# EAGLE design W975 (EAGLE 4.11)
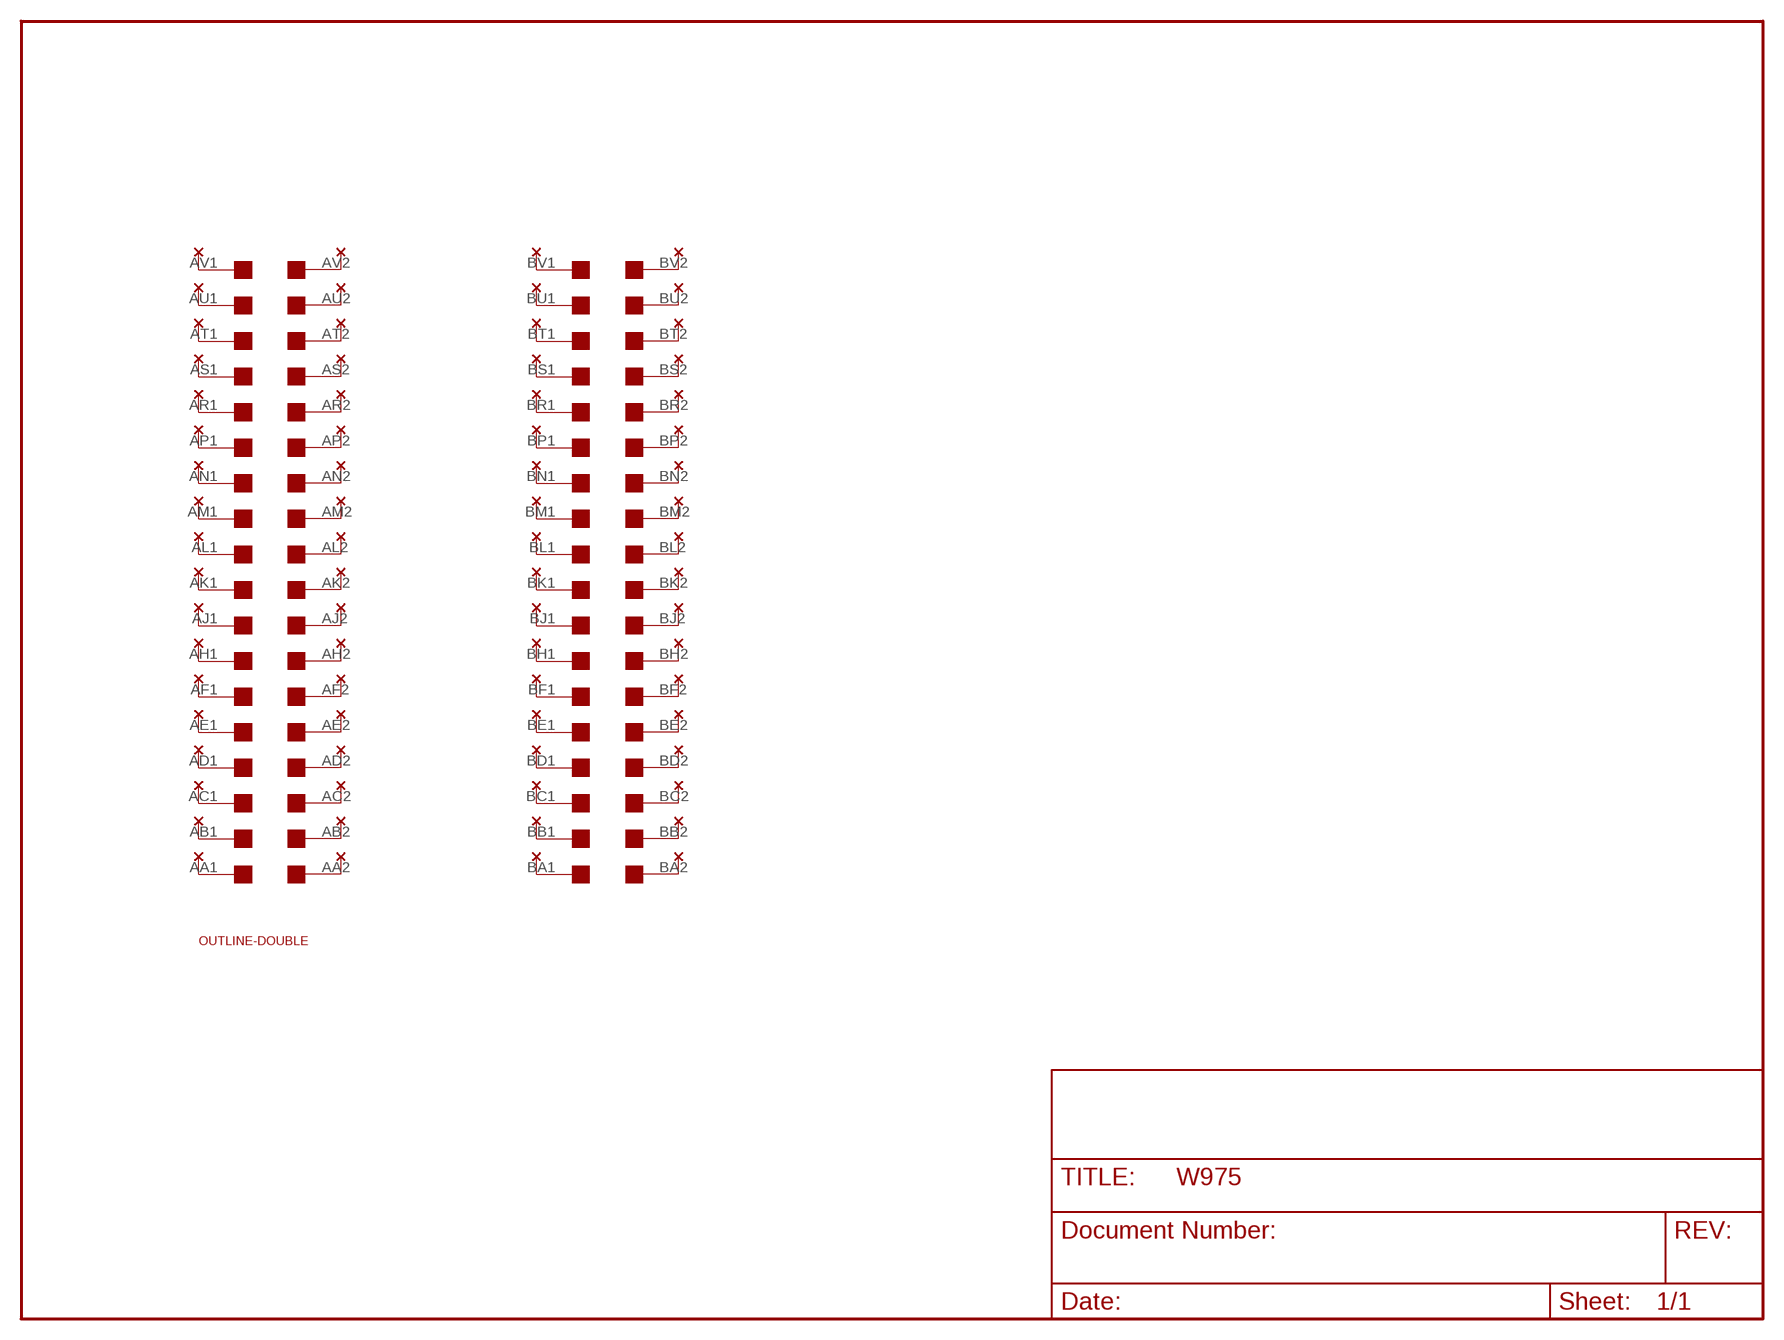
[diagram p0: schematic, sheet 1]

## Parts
A  A  THRU-HOLE2  [THRU-HOLE2]
B  B  THRU-HOLE2  [THRU-HOLE2]
U$1  OUTLINE-DOUBLE  [DOUBLE]
U$2  DOUBLE  [EDGE-CON4]

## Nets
N$1: A.K2 U$2.AK2
N$2: A.J2 U$2.AJ2
N$3: A.H2 U$2.AH2
N$4: A.L2 U$2.AL2
N$5: A.M2 U$2.AM2
N$6: A.N2 U$2.AN2
N$7: A.P2 U$2.AP2
N$8: A.F2 U$2.AF2
N$9: A.E2 U$2.AE2
N$10: A.D2 U$2.AD2
N$11: A.C2 U$2.AC2
N$12: A.R2 U$2.AR2
N$13: A.S2 U$2.AS2
N$14: A.B2 U$2.AB2
N$15: A.A2 U$2.AA2
N$16: A.T2 U$2.AT2
N$17: A.U2 U$2.AU2
N$18: A.V2 U$2.AV2
N$19: A.A1 U$2.AA1
N$20: A.V1 U$2.AV1
N$21: A.U1 U$2.AU1
N$22: A.T1 U$2.AT1
N$23: A.S1 U$2.AS1
N$24: A.R1 U$2.AR1
N$25: A.P1 U$2.AP1
N$26: A.N1 U$2.AN1
N$27: A.M1 U$2.AM1
N$28: A.L1 U$2.AL1
N$29: A.K1 U$2.AK1
N$30: A.J1 U$2.AJ1
N$31: A.H1 U$2.AH1
N$32: A.F1 U$2.AF1
N$33: A.E1 U$2.AE1
N$34: A.D1 U$2.AD1
N$35: A.C1 U$2.AC1
N$36: A.B1 U$2.AB1
N$37: B.K2 U$2.BK2
N$38: B.J2 U$2.BJ2
N$39: B.H2 U$2.BH2
N$40: B.L2 U$2.BL2
N$41: B.M2 U$2.BM2
N$42: B.N2 U$2.BN2
N$43: B.P2 U$2.BP2
N$44: B.F2 U$2.BF2
N$45: B.E2 U$2.BE2
N$46: B.D2 U$2.BD2
N$47: B.C2 U$2.BC2
N$48: B.R2 U$2.BR2
N$49: B.S2 U$2.BS2
N$50: B.B2 U$2.BB2
N$51: B.A2 U$2.BA2
N$52: B.T2 U$2.BT2
N$53: B.U2 U$2.BU2
N$54: B.V2 U$2.BV2
N$55: B.A1 U$2.BA1
N$56: B.V1 U$2.BV1
N$57: B.U1 U$2.BU1
N$58: B.T1 U$2.BT1
N$59: B.S1 U$2.BS1
N$60: B.R1 U$2.BR1
N$61: B.P1 U$2.BP1
N$62: B.N1 U$2.BN1
N$63: B.M1 U$2.BM1
N$64: B.L1 U$2.BL1
N$65: B.K1 U$2.BK1
N$66: B.J1 U$2.BJ1
N$67: B.H1 U$2.BH1
N$68: B.F1 U$2.BF1
N$69: B.E1 U$2.BE1
N$70: B.D1 U$2.BD1
N$71: B.C1 U$2.BC1
N$72: B.B1 U$2.BB1

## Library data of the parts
A B = dec-con:THRU-HOLE2: Thru-Hole addition to double-sided edge connector.
U$1 = dec-con:OUTLINE-*: Board outlines for DEC boards.
U$2 = dec-con:DOUBLE: Double-Height DEC board

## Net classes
0 default: width 0.508 mm, drill 0.508 mm

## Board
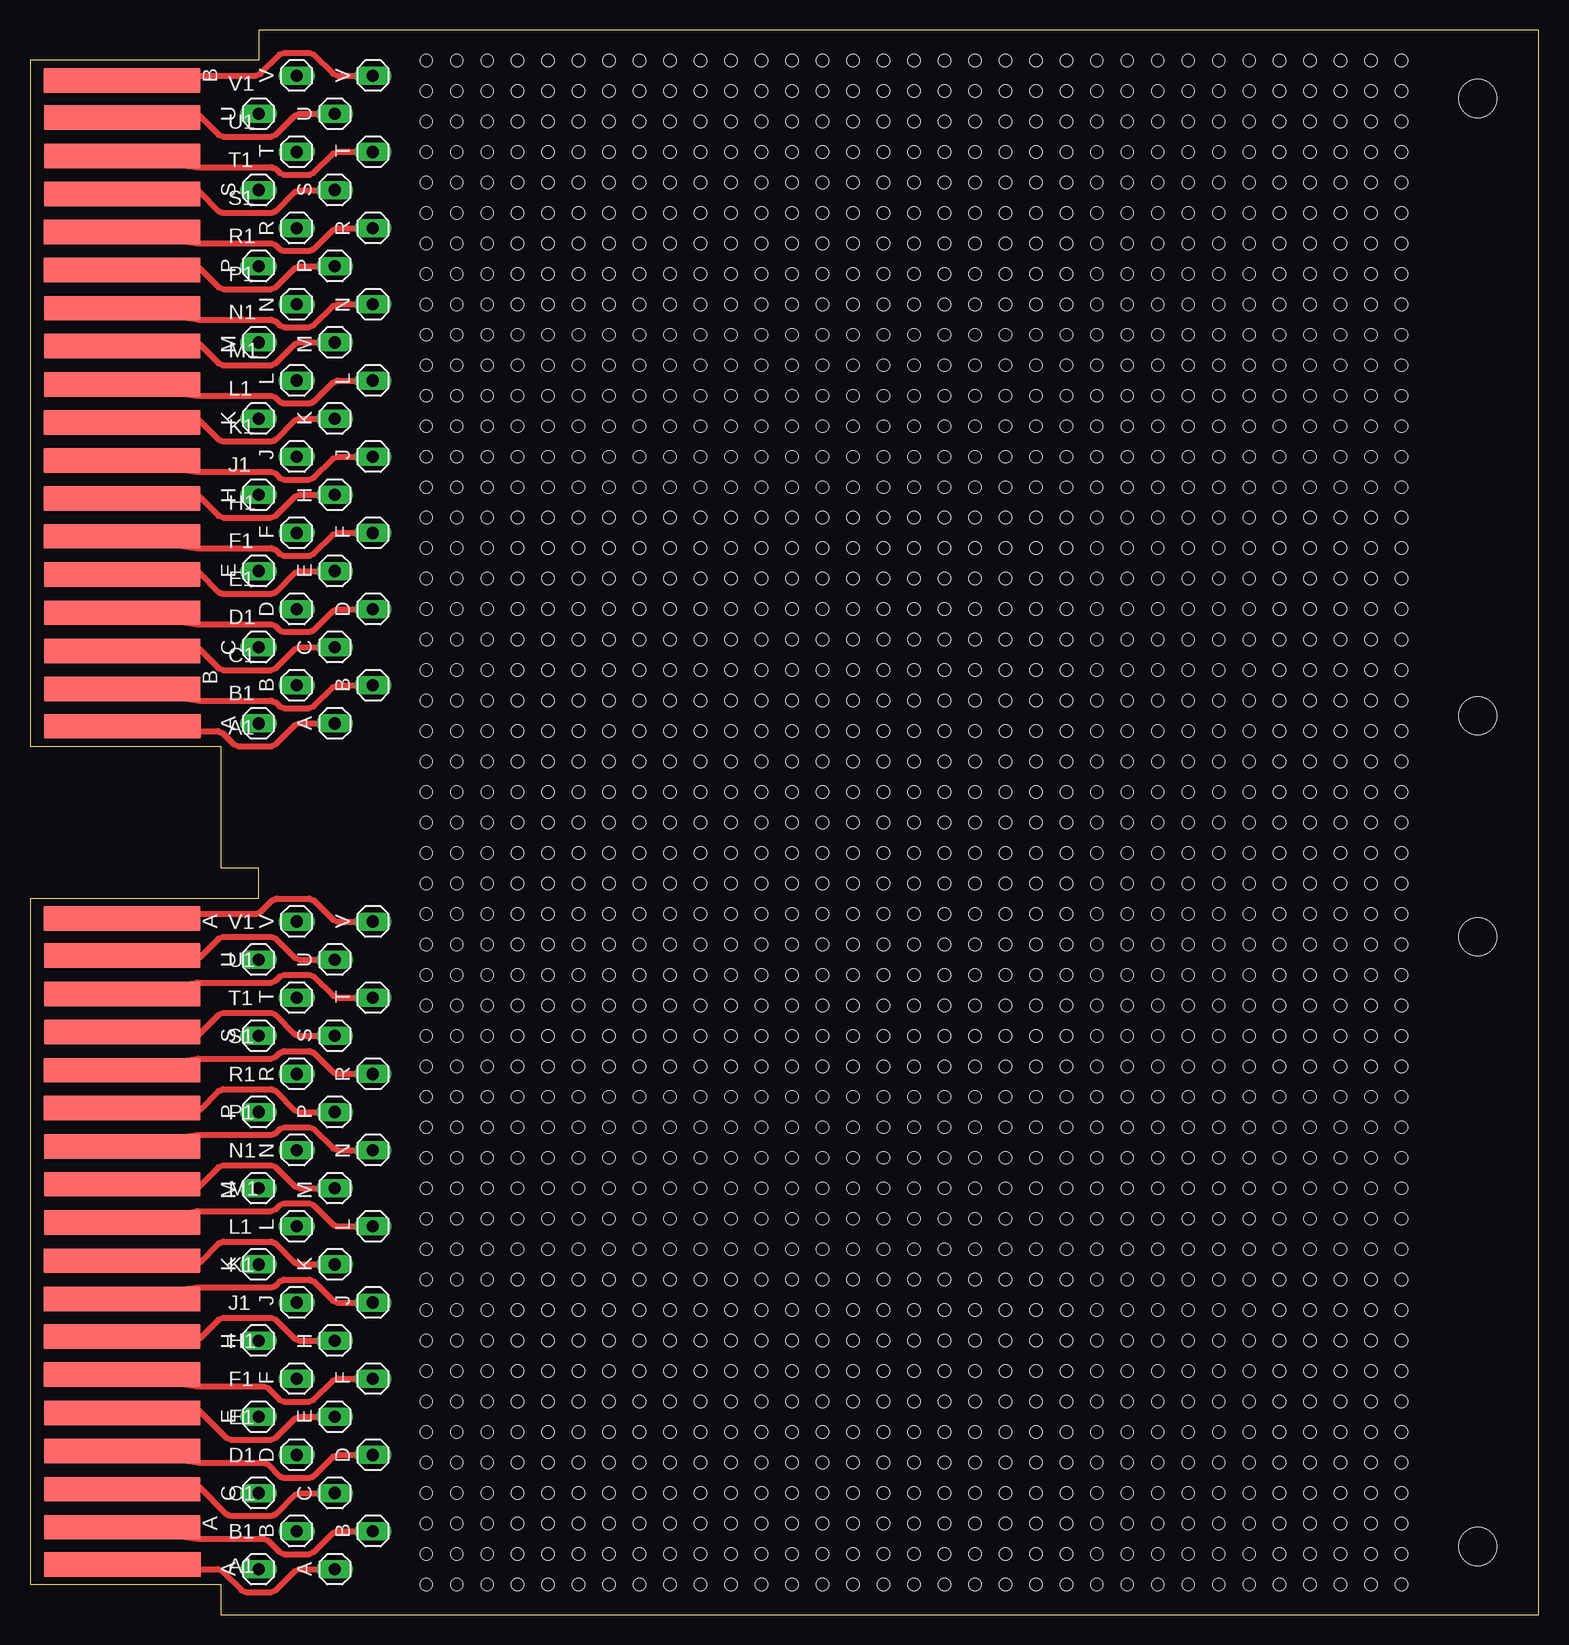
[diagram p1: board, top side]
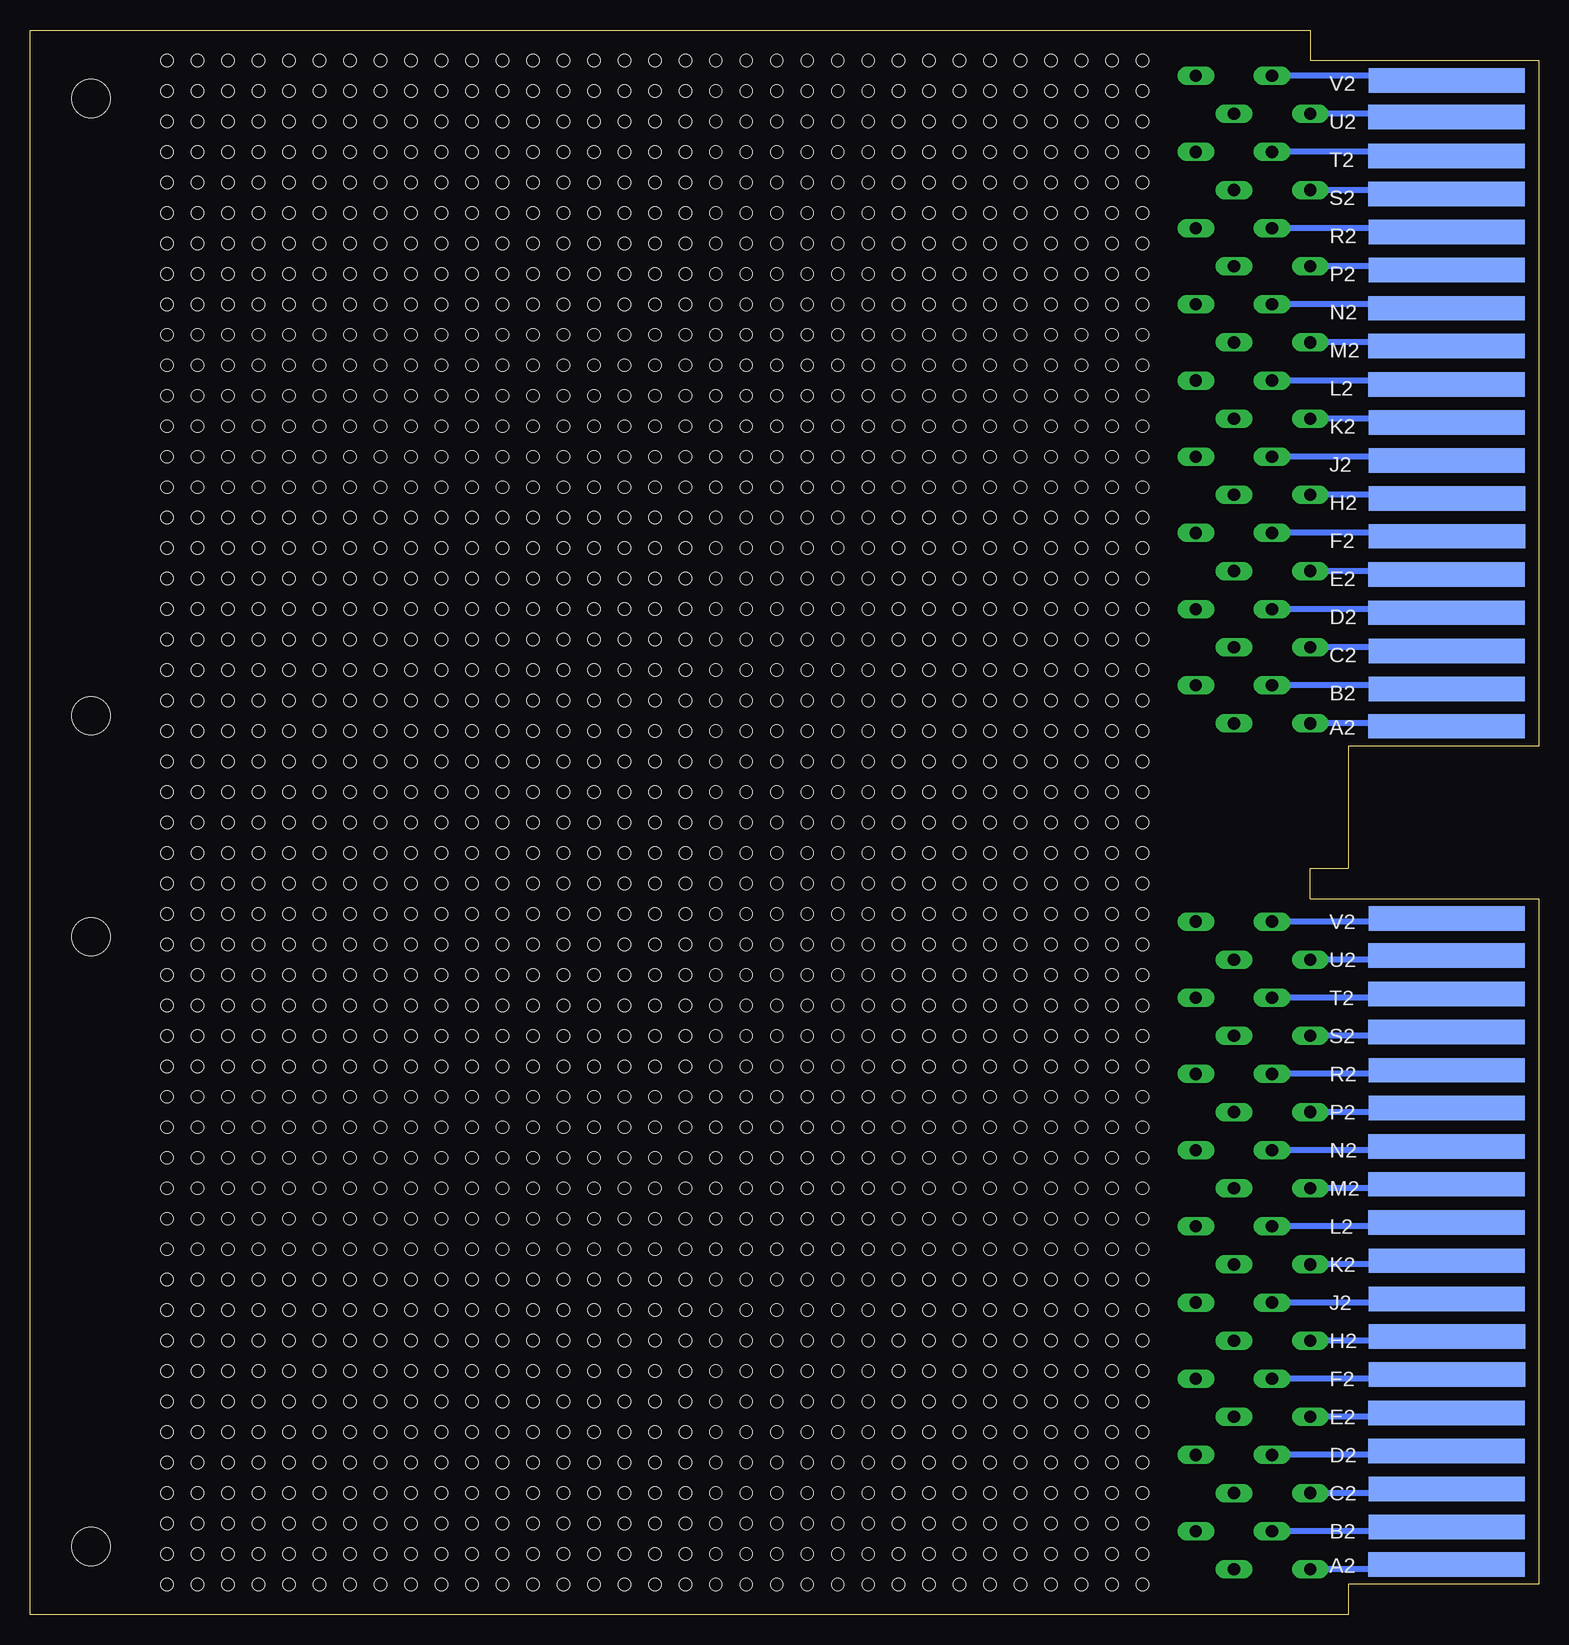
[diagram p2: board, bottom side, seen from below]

Size 125.73 x 132.08 mm. Coordinates in mm from the lower left corner, seen from the top.
Copper layers (1*16): Top 0.035mm / dielectric 1.5mm / Bottom 0.035mm
Design rules "15mils": minimum track width 15mil, minimum drill 24mil, track to track 15mil, track to pad 10mil, pad to pad 10mil, via to via 10mil, smd to smd 10mil, copper to edge 25mil, drill to drill 10mil, minimum pad ring 10mil, minimum via ring 8mil, stop-mask expansion 0mil, vias tented up to drill 0mil, thermal gap 10mil
Holes 1.02 mm at 33.02,129.54 33.02,127 35.56,127 35.56,129.54 33.02,124.46 35.56,124.46 38.1,124.46 38.1,127 38.1,129.54 40.64,129.54 40.64,127 43.18,127 43.18,129.54 40.64,124.46 43.18,124.46 45.72,124.46 45.72,127 45.72,129.54 33.02,121.92 33.02,119.38 35.56,119.38 35.56,121.92 33.02,116.84 35.56,116.84 38.1,116.84 38.1,119.38 38.1,121.92 40.64,121.92 40.64,119.38 43.18,119.38 43.18,121.92 40.64,116.84 43.18,116.84 45.72,116.84 45.72,119.38 45.72,121.92 48.26,129.54 48.26,127 50.8,127 50.8,129.54 48.26,124.46 50.8,124.46 53.34,124.46 53.34,127 53.34,129.54 55.88,129.54 55.88,127 58.42,127 58.42,129.54 55.88,124.46 58.42,124.46 60.96,124.46 60.96,127 60.96,129.54 48.26,121.92 48.26,119.38 50.8,119.38 50.8,121.92 48.26,116.84 50.8,116.84 53.34,116.84 53.34,119.38 53.34,121.92 55.88,121.92 55.88,119.38 58.42,119.38 58.42,121.92 55.88,116.84 58.42,116.84 60.96,116.84 60.96,119.38 60.96,121.92 63.5,129.54 63.5,127 66.04,127 66.04,129.54 63.5,124.46 66.04,124.46 68.58,124.46 68.58,127 68.58,129.54 71.12,129.54 71.12,127 73.66,127 73.66,129.54 71.12,124.46 73.66,124.46 76.2,124.46 76.2,127 76.2,129.54 63.5,121.92 63.5,119.38 66.04,119.38 66.04,121.92 63.5,116.84 66.04,116.84 68.58,116.84 68.58,119.38 68.58,121.92 71.12,121.92 71.12,119.38 73.66,119.38 73.66,121.92 71.12,116.84 73.66,116.84 76.2,116.84 76.2,119.38 76.2,121.92 78.74,129.54 78.74,127 81.28,127 81.28,129.54 78.74,124.46 81.28,124.46 83.82,124.46 83.82,127 83.82,129.54 86.36,129.54 86.36,127 88.9,127 88.9,129.54 86.36,124.46 88.9,124.46 91.44,124.46 91.44,127 91.44,129.54 78.74,121.92 78.74,119.38 81.28,119.38 81.28,121.92 78.74,116.84 81.28,116.84 83.82,116.84 83.82,119.38 83.82,121.92 86.36,121.92 86.36,119.38 88.9,119.38 88.9,121.92 86.36,116.84 88.9,116.84 91.44,116.84 91.44,119.38 91.44,121.92 93.98,129.54 93.98,127 96.52,127 96.52,129.54 93.98,124.46 96.52,124.46 99.06,124.46 99.06,127 99.06,129.54 101.6,129.54 101.6,127 104.14,127 104.14,129.54 101.6,124.46 104.14,124.46 106.68,124.46 106.68,127 106.68,129.54 93.98,121.92 93.98,119.38 96.52,119.38 96.52,121.92 93.98,116.84 96.52,116.84 99.06,116.84 99.06,119.38 99.06,121.92 101.6,121.92 101.6,119.38 104.14,119.38 104.14,121.92 101.6,116.84 104.14,116.84 106.68,116.84 106.68,119.38 106.68,121.92 109.22,124.46 109.22,127 109.22,129.54 111.76,129.54 111.76,127 114.3,127 114.3,129.54 111.76,124.46 114.3,124.46 109.22,116.84 109.22,119.38 109.22,121.92 111.76,121.92 111.76,119.38 114.3,119.38 114.3,121.92 111.76,116.84 114.3,116.84 33.02,114.3 33.02,111.76 35.56,111.76 35.56,114.3 33.02,109.22 35.56,109.22 38.1,109.22 38.1,111.76 38.1,114.3 40.64,114.3 40.64,111.76 43.18,111.76 43.18,114.3 40.64,109.22 43.18,109.22 45.72,109.22 45.72,111.76 45.72,114.3 33.02,106.68 33.02,104.14 35.56,104.14 35.56,106.68 33.02,101.6 35.56,101.6 38.1,101.6 38.1,104.14 38.1,106.68 40.64,106.68 40.64,104.14 43.18,104.14 43.18,106.68 40.64,101.6 43.18,101.6 45.72,101.6 45.72,104.14 45.72,106.68 48.26,114.3 48.26,111.76 50.8,111.76 50.8,114.3 48.26,109.22 50.8,109.22 53.34,109.22 53.34,111.76 53.34,114.3 55.88,114.3 55.88,111.76 58.42,111.76 58.42,114.3 55.88,109.22 58.42,109.22 60.96,109.22 60.96,111.76 60.96,114.3 48.26,106.68 48.26,104.14 50.8,104.14 50.8,106.68 48.26,101.6 50.8,101.6 53.34,101.6 53.34,104.14 53.34,106.68 55.88,106.68 55.88,104.14 58.42,104.14 58.42,106.68 55.88,101.6 58.42,101.6 60.96,101.6 60.96,104.14 60.96,106.68 63.5,114.3 63.5,111.76 66.04,111.76 66.04,114.3 63.5,109.22 66.04,109.22 68.58,109.22 68.58,111.76 68.58,114.3 71.12,114.3 71.12,111.76 73.66,111.76 73.66,114.3 71.12,109.22 73.66,109.22 76.2,109.22 76.2,111.76 76.2,114.3 63.5,106.68 63.5,104.14 66.04,104.14 66.04,106.68 63.5,101.6 66.04,101.6 68.58,101.6 68.58,104.14 68.58,106.68 71.12,106.68 71.12,104.14 73.66,104.14 73.66,106.68 71.12,101.6 73.66,101.6 76.2,101.6 76.2,104.14 76.2,106.68 78.74,114.3 78.74,111.76 81.28,111.76 81.28,114.3 78.74,109.22 81.28,109.22 83.82,109.22 83.82,111.76 83.82,114.3 86.36,114.3 86.36,111.76 88.9,111.76 88.9,114.3 86.36,109.22 88.9,109.22 91.44,109.22 91.44,111.76 91.44,114.3 78.74,106.68 78.74,104.14 81.28,104.14 81.28,106.68 78.74,101.6 81.28,101.6 83.82,101.6 83.82,104.14 83.82,106.68 86.36,106.68 86.36,104.14 88.9,104.14 88.9,106.68 86.36,101.6 88.9,101.6 91.44,101.6 91.44,104.14 91.44,106.68 93.98,114.3 93.98,111.76 96.52,111.76 96.52,114.3 93.98,109.22 96.52,109.22 99.06,109.22 99.06,111.76 99.06,114.3 101.6,114.3 101.6,111.76 104.14,111.76 104.14,114.3 101.6,109.22 104.14,109.22 106.68,109.22 106.68,111.76 106.68,114.3 93.98,106.68 93.98,104.14 96.52,104.14 96.52,106.68 93.98,101.6 96.52,101.6 99.06,101.6 99.06,104.14 99.06,106.68 101.6,106.68 101.6,104.14 104.14,104.14 104.14,106.68 101.6,101.6 104.14,101.6 106.68,101.6 106.68,104.14 106.68,106.68 109.22,109.22 109.22,111.76 109.22,114.3 111.76,114.3 111.76,111.76 114.3,111.76 114.3,114.3 111.76,109.22 114.3,109.22 109.22,101.6 109.22,104.14 109.22,106.68 111.76,106.68 111.76,104.14 114.3,104.14 114.3,106.68 111.76,101.6 114.3,101.6 33.02,99.06 33.02,96.52 35.56,96.52 35.56,99.06 33.02,93.98 35.56,93.98 38.1,93.98 38.1,96.52 38.1,99.06 40.64,99.06 40.64,96.52 43.18,96.52 43.18,99.06 40.64,93.98 43.18,93.98 45.72,93.98 45.72,96.52 45.72,99.06 33.02,91.44 33.02,88.9 35.56,88.9 35.56,91.44 33.02,86.36 35.56,86.36 38.1,86.36 38.1,88.9 38.1,91.44 40.64,91.44 40.64,88.9 43.18,88.9 43.18,91.44 40.64,86.36 43.18,86.36 45.72,86.36 45.72,88.9 45.72,91.44 48.26,99.06 48.26,96.52 50.8,96.52 50.8,99.06 48.26,93.98 50.8,93.98 53.34,93.98 53.34,96.52 53.34,99.06 55.88,99.06 55.88,96.52 58.42,96.52 58.42,99.06 55.88,93.98 58.42,93.98 60.96,93.98 60.96,96.52 60.96,99.06 48.26,91.44 48.26,88.9 50.8,88.9 50.8,91.44 48.26,86.36 50.8,86.36 53.34,86.36 53.34,88.9 53.34,91.44 55.88,91.44 55.88,88.9 58.42,88.9 58.42,91.44 55.88,86.36 58.42,86.36 60.96,86.36 60.96,88.9 60.96,91.44 63.5,99.06 63.5,96.52 66.04,96.52 66.04,99.06 63.5,93.98 66.04,93.98 68.58,93.98 68.58,96.52 68.58,99.06 71.12,99.06 71.12,96.52 73.66,96.52 73.66,99.06 71.12,93.98 73.66,93.98 76.2,93.98 76.2,96.52 76.2,99.06 63.5,91.44 63.5,88.9 66.04,88.9 66.04,91.44 63.5,86.36 66.04,86.36 68.58,86.36 68.58,88.9 68.58,91.44 71.12,91.44 71.12,88.9 73.66,88.9 73.66,91.44 71.12,86.36 73.66,86.36 76.2,86.36 76.2,88.9 76.2,91.44 78.74,99.06 78.74,96.52 81.28,96.52 81.28,99.06 78.74,93.98 81.28,93.98 83.82,93.98 83.82,96.52 83.82,99.06 86.36,99.06 86.36,96.52 88.9,96.52 88.9,99.06 86.36,93.98 88.9,93.98 91.44,93.98 91.44,96.52 91.44,99.06 78.74,91.44 78.74,88.9 81.28,88.9 81.28,91.44 78.74,86.36 81.28,86.36 83.82,86.36 83.82,88.9 83.82,91.44 86.36,91.44 86.36,88.9 88.9,88.9 88.9,91.44 86.36,86.36 88.9,86.36 91.44,86.36 91.44,88.9 91.44,91.44 93.98,99.06 93.98,96.52 96.52,96.52 96.52,99.06 93.98,93.98 96.52,93.98 99.06,93.98 99.06,96.52 99.06,99.06 101.6,99.06 101.6,96.52 104.14,96.52 104.14,99.06 101.6,93.98 104.14,93.98 106.68,93.98 106.68,96.52 106.68,99.06 93.98,91.44 93.98,88.9 96.52,88.9 96.52,91.44 93.98,86.36 96.52,86.36 99.06,86.36 99.06,88.9 99.06,91.44 101.6,91.44 101.6,88.9 104.14,88.9 104.14,91.44 101.6,86.36 104.14,86.36 106.68,86.36 106.68,88.9 106.68,91.44 109.22,93.98 109.22,96.52 109.22,99.06 111.76,99.06 111.76,96.52 114.3,96.52 114.3,99.06 111.76,93.98 114.3,93.98 109.22,86.36 109.22,88.9 109.22,91.44 111.76,91.44 111.76,88.9 114.3,88.9 114.3,91.44 111.76,86.36 114.3,86.36 33.02,83.82 33.02,81.28 35.56,81.28 35.56,83.82 33.02,78.74 35.56,78.74 38.1,78.74 38.1,81.28 38.1,83.82 40.64,83.82 40.64,81.28 43.18,81.28 43.18,83.82 40.64,78.74 43.18,78.74 45.72,78.74 45.72,81.28 45.72,83.82 33.02,76.2 33.02,73.66 35.56,73.66 35.56,76.2 33.02,71.12 35.56,71.12 38.1,71.12 38.1,73.66 38.1,76.2 40.64,76.2 40.64,73.66 43.18,73.66 43.18,76.2 40.64,71.12 43.18,71.12 45.72,71.12 45.72,73.66 45.72,76.2 48.26,83.82 48.26,81.28 50.8,81.28 50.8,83.82 48.26,78.74 50.8,78.74 53.34,78.74 53.34,81.28 53.34,83.82 55.88,83.82 55.88,81.28 58.42,81.28 58.42,83.82 55.88,78.74 58.42,78.74 60.96,78.74 60.96,81.28 60.96,83.82 48.26,76.2 48.26,73.66 50.8,73.66 50.8,76.2 48.26,71.12 50.8,71.12 53.34,71.12 53.34,73.66 53.34,76.2 55.88,76.2 55.88,73.66 58.42,73.66 58.42,76.2 55.88,71.12 58.42,71.12 60.96,71.12 60.96,73.66 60.96,76.2 63.5,83.82 63.5,81.28 66.04,81.28 66.04,83.82 63.5,78.74 66.04,78.74 68.58,78.74 68.58,81.28 68.58,83.82 71.12,83.82 71.12,81.28 73.66,81.28 73.66,83.82 71.12,78.74 73.66,78.74 76.2,78.74 76.2,81.28 76.2,83.82 63.5,76.2 63.5,73.66 66.04,73.66 66.04,76.2 63.5,71.12 66.04,71.12 68.58,71.12 68.58,73.66 68.58,76.2 71.12,76.2 71.12,73.66 73.66,73.66 73.66,76.2 71.12,71.12 73.66,71.12 76.2,71.12 76.2,73.66 76.2,76.2 78.74,83.82 78.74,81.28 81.28,81.28 81.28,83.82 78.74,78.74 81.28,78.74 83.82,78.74 83.82,81.28 83.82,83.82 86.36,83.82 86.36,81.28 88.9,81.28 88.9,83.82 86.36,78.74 88.9,78.74 91.44,78.74 91.44,81.28 91.44,83.82 78.74,76.2 78.74,73.66 81.28,73.66 81.28,76.2 78.74,71.12 81.28,71.12 83.82,71.12 83.82,73.66 83.82,76.2 86.36,76.2 86.36,73.66 88.9,73.66 88.9,76.2 86.36,71.12 88.9,71.12 91.44,71.12 91.44,73.66 91.44,76.2 93.98,83.82 93.98,81.28 96.52,81.28 96.52,83.82 93.98,78.74 96.52,78.74 99.06,78.74 99.06,81.28 99.06,83.82 101.6,83.82 101.6,81.28 104.14,81.28 104.14,83.82 101.6,78.74 104.14,78.74 106.68,78.74 106.68,81.28 106.68,83.82 93.98,76.2 93.98,73.66 96.52,73.66 96.52,76.2 93.98,71.12 96.52,71.12 99.06,71.12 99.06,73.66 99.06,76.2 101.6,76.2 101.6,73.66 104.14,73.66 104.14,76.2 101.6,71.12 104.14,71.12 106.68,71.12 106.68,73.66 106.68,76.2 109.22,78.74 109.22,81.28 109.22,83.82 111.76,83.82 111.76,81.28 114.3,81.28 114.3,83.82 111.76,78.74 114.3,78.74 109.22,71.12 109.22,73.66 109.22,76.2 111.76,76.2 111.76,73.66 114.3,73.66 114.3,76.2 111.76,71.12 114.3,71.12 33.02,68.58 33.02,66.04 35.56,66.04 35.56,68.58 33.02,63.5 35.56,63.5 38.1,63.5 38.1,66.04 38.1,68.58 40.64,68.58 40.64,66.04 43.18,66.04 43.18,68.58 40.64,63.5 43.18,63.5 45.72,63.5 45.72,66.04 45.72,68.58 33.02,60.96 33.02,58.42 35.56,58.42 35.56,60.96 33.02,55.88 35.56,55.88 38.1,55.88 38.1,58.42 38.1,60.96 40.64,60.96 40.64,58.42 43.18,58.42 43.18,60.96 40.64,55.88 43.18,55.88 45.72,55.88 45.72,58.42 45.72,60.96 48.26,68.58 48.26,66.04 50.8,66.04 50.8,68.58 48.26,63.5 50.8,63.5 53.34,63.5 53.34,66.04 53.34,68.58 55.88,68.58 55.88,66.04 58.42,66.04 58.42,68.58 55.88,63.5 58.42,63.5 60.96,63.5 60.96,66.04 60.96,68.58 48.26,60.96 48.26,58.42 50.8,58.42 50.8,60.96 48.26,55.88 50.8,55.88 53.34,55.88 53.34,58.42 53.34,60.96 55.88,60.96 55.88,58.42 58.42,58.42 58.42,60.96 55.88,55.88 58.42,55.88 60.96,55.88 60.96,58.42 60.96,60.96 63.5,68.58 63.5,66.04 66.04,66.04 66.04,68.58 63.5,63.5 66.04,63.5 68.58,63.5 68.58,66.04 68.58,68.58 71.12,68.58 71.12,66.04 73.66,66.04 73.66,68.58 71.12,63.5 73.66,63.5 76.2,63.5 76.2,66.04 76.2,68.58 63.5,60.96 63.5,58.42 66.04,58.42 66.04,60.96 63.5,55.88 66.04,55.88 68.58,55.88 68.58,58.42 68.58,60.96 71.12,60.96 71.12,58.42 73.66,58.42 73.66,60.96 71.12,55.88 73.66,55.88 76.2,55.88 76.2,58.42 76.2,60.96 78.74,68.58 78.74,66.04 81.28,66.04 81.28,68.58 78.74,63.5 81.28,63.5 83.82,63.5 83.82,66.04 83.82,68.58 86.36,68.58 86.36,66.04 88.9,66.04 88.9,68.58 86.36,63.5 88.9,63.5 91.44,63.5 91.44,66.04 91.44,68.58 78.74,60.96 78.74,58.42 81.28,58.42 81.28,60.96 78.74,55.88 81.28,55.88 83.82,55.88 83.82,58.42 83.82,60.96 86.36,60.96 86.36,58.42 88.9,58.42 88.9,60.96 86.36,55.88 88.9,55.88 91.44,55.88 91.44,58.42 91.44,60.96 93.98,68.58 93.98,66.04 96.52,66.04 96.52,68.58 93.98,63.5 96.52,63.5 99.06,63.5 99.06,66.04 99.06,68.58 101.6,68.58 101.6,66.04 104.14,66.04 104.14,68.58 101.6,63.5 104.14,63.5 106.68,63.5 106.68,66.04 106.68,68.58 93.98,60.96 93.98,58.42 96.52,58.42 96.52,60.96 93.98,55.88 96.52,55.88 99.06,55.88 99.06,58.42 99.06,60.96 101.6,60.96 101.6,58.42 104.14,58.42 104.14,60.96 101.6,55.88 104.14,55.88 106.68,55.88 106.68,58.42 106.68,60.96 109.22,63.5 109.22,66.04 109.22,68.58 111.76,68.58 111.76,66.04 114.3,66.04 114.3,68.58 111.76,63.5 114.3,63.5 109.22,55.88 109.22,58.42 109.22,60.96 111.76,60.96 111.76,58.42 114.3,58.42 114.3,60.96 111.76,55.88 114.3,55.88 33.02,53.34 33.02,50.8 35.56,50.8 35.56,53.34 33.02,48.26 35.56,48.26 38.1,48.26 38.1,50.8 38.1,53.34 40.64,53.34 40.64,50.8 43.18,50.8 43.18,53.34 40.64,48.26 43.18,48.26 45.72,48.26 45.72,50.8 45.72,53.34 33.02,45.72 33.02,43.18 35.56,43.18 35.56,45.72 33.02,40.64 35.56,40.64 38.1,40.64 38.1,43.18 38.1,45.72 40.64,45.72 40.64,43.18 43.18,43.18 43.18,45.72 40.64,40.64 43.18,40.64 45.72,40.64 45.72,43.18 45.72,45.72 48.26,53.34 48.26,50.8 50.8,50.8 50.8,53.34 48.26,48.26 50.8,48.26 53.34,48.26 53.34,50.8 53.34,53.34 55.88,53.34 55.88,50.8 58.42,50.8 58.42,53.34 55.88,48.26 58.42,48.26 60.96,48.26 60.96,50.8 60.96,53.34 48.26,45.72 48.26,43.18 50.8,43.18 50.8,45.72 48.26,40.64 50.8,40.64 53.34,40.64 53.34,43.18 53.34,45.72 55.88,45.72 55.88,43.18 58.42,43.18 58.42,45.72 55.88,40.64 58.42,40.64 60.96,40.64 60.96,43.18 60.96,45.72 63.5,53.34 63.5,50.8 66.04,50.8 66.04,53.34 63.5,48.26 66.04,48.26 68.58,48.26 68.58,50.8 68.58,53.34 71.12,53.34 71.12,50.8 73.66,50.8 73.66,53.34 71.12,48.26 73.66,48.26 76.2,48.26 76.2,50.8 76.2,53.34 63.5,45.72 63.5,43.18 66.04,43.18 66.04,45.72 63.5,40.64 66.04,40.64 68.58,40.64 68.58,43.18 68.58,45.72 71.12,45.72 71.12,43.18 73.66,43.18 73.66,45.72 71.12,40.64 73.66,40.64 76.2,40.64 76.2,43.18 76.2,45.72 78.74,53.34 78.74,50.8 81.28,50.8 81.28,53.34 78.74,48.26 81.28,48.26 83.82,48.26 83.82,50.8 83.82,53.34 86.36,53.34 86.36,50.8 88.9,50.8 88.9,53.34 86.36,48.26 88.9,48.26 91.44,48.26 91.44,50.8 91.44,53.34 78.74,45.72 78.74,43.18 81.28,43.18 81.28,45.72 78.74,40.64 81.28,40.64 83.82,40.64 83.82,43.18 83.82,45.72 86.36,45.72 86.36,43.18 88.9,43.18 88.9,45.72 86.36,40.64 88.9,40.64 91.44,40.64 91.44,43.18 91.44,45.72 93.98,53.34 93.98,50.8 96.52,50.8 96.52,53.34 93.98,48.26 96.52,48.26 99.06,48.26 99.06,50.8 99.06,53.34 101.6,53.34 101.6,50.8 104.14,50.8 104.14,53.34 101.6,48.26 104.14,48.26 106.68,48.26 106.68,50.8 106.68,53.34 93.98,45.72 93.98,43.18 96.52,43.18 96.52,45.72 93.98,40.64 96.52,40.64 99.06,40.64 99.06,43.18 99.06,45.72 101.6,45.72 101.6,43.18 104.14,43.18 104.14,45.72 101.6,40.64 104.14,40.64 106.68,40.64 106.68,43.18 106.68,45.72 109.22,48.26 109.22,50.8 109.22,53.34 111.76,53.34 111.76,50.8 114.3,50.8 114.3,53.34 111.76,48.26 114.3,48.26 109.22,40.64 109.22,43.18 109.22,45.72 111.76,45.72 111.76,43.18 114.3,43.18 114.3,45.72 111.76,40.64 114.3,40.64 33.02,38.1 33.02,35.56 35.56,35.56 35.56,38.1 33.02,33.02 35.56,33.02 38.1,33.02 38.1,35.56 38.1,38.1 40.64,38.1 40.64,35.56 43.18,35.56 43.18,38.1 40.64,33.02 43.18,33.02 45.72,33.02 45.72,35.56 45.72,38.1 33.02,30.48 33.02,27.94 35.56,27.94 35.56,30.48 33.02,25.4 35.56,25.4 38.1,25.4 38.1,27.94 38.1,30.48 40.64,30.48 40.64,27.94 43.18,27.94 43.18,30.48 40.64,25.4 43.18,25.4 45.72,25.4 45.72,27.94 45.72,30.48 48.26,38.1 48.26,35.56 50.8,35.56 50.8,38.1 48.26,33.02 50.8,33.02 53.34,33.02 53.34,35.56 53.34,38.1 55.88,38.1 55.88,35.56 58.42,35.56 58.42,38.1 55.88,33.02 58.42,33.02 60.96,33.02 60.96,35.56 60.96,38.1 48.26,30.48 48.26,27.94 50.8,27.94 50.8,30.48 48.26,25.4 50.8,25.4 53.34,25.4 53.34,27.94 53.34,30.48 55.88,30.48 55.88,27.94 58.42,27.94 58.42,30.48 55.88,25.4 58.42,25.4 60.96,25.4 60.96,27.94 60.96,30.48 63.5,38.1 63.5,35.56 66.04,35.56 66.04,38.1 63.5,33.02 66.04,33.02 68.58,33.02 68.58,35.56 68.58,38.1 71.12,38.1 71.12,35.56 73.66,35.56 73.66,38.1 71.12,33.02 73.66,33.02 76.2,33.02 76.2,35.56 76.2,38.1 63.5,30.48 63.5,27.94 66.04,27.94 66.04,30.48 63.5,25.4 66.04,25.4 68.58,25.4 68.58,27.94 68.58,30.48 71.12,30.48 71.12,27.94 73.66,27.94 73.66,30.48 71.12,25.4 73.66,25.4 76.2,25.4 76.2,27.94 76.2,30.48 78.74,38.1 78.74,35.56 81.28,35.56 81.28,38.1 78.74,33.02 81.28,33.02 83.82,33.02 83.82,35.56 83.82,38.1 86.36,38.1 86.36,35.56 88.9,35.56 88.9,38.1 86.36,33.02 88.9,33.02 91.44,33.02 91.44,35.56 91.44,38.1 78.74,30.48 78.74,27.94 81.28,27.94 81.28,30.48 78.74,25.4 81.28,25.4 83.82,25.4 83.82,27.94 83.82,30.48 86.36,30.48 86.36,27.94 88.9,27.94 88.9,30.48 86.36,25.4 88.9,25.4 91.44,25.4 91.44,27.94 91.44,30.48 93.98,38.1 93.98,35.56 96.52,35.56 96.52,38.1 93.98,33.02 96.52,33.02 99.06,33.02 99.06,35.56 99.06,38.1 101.6,38.1 101.6,35.56 104.14,35.56 104.14,38.1 101.6,33.02 104.14,33.02 106.68,33.02 106.68,35.56 106.68,38.1 93.98,30.48 93.98,27.94 96.52,27.94 96.52,30.48 93.98,25.4 96.52,25.4 99.06,25.4 99.06,27.94 99.06,30.48 101.6,30.48 101.6,27.94 104.14,27.94 104.14,30.48 101.6,25.4 104.14,25.4 106.68,25.4 106.68,27.94 106.68,30.48 109.22,33.02 109.22,35.56 109.22,38.1 111.76,38.1 111.76,35.56 114.3,35.56 114.3,38.1 111.76,33.02 114.3,33.02 109.22,25.4 109.22,27.94 109.22,30.48 111.76,30.48 111.76,27.94 114.3,27.94 114.3,30.48 111.76,25.4 114.3,25.4 33.02,22.86 33.02,20.32 35.56,20.32 35.56,22.86 33.02,17.78 35.56,17.78 38.1,17.78 38.1,20.32 38.1,22.86 40.64,22.86 40.64,20.32 43.18,20.32 43.18,22.86 40.64,17.78 43.18,17.78 45.72,17.78 45.72,20.32 45.72,22.86 33.02,15.24 33.02,12.7 35.56,12.7 35.56,15.24 33.02,10.16 35.56,10.16 38.1,10.16 38.1,12.7 38.1,15.24 40.64,15.24 40.64,12.7 43.18,12.7 43.18,15.24 40.64,10.16 43.18,10.16 45.72,10.16 45.72,12.7 45.72,15.24 48.26,22.86 48.26,20.32 50.8,20.32 50.8,22.86 48.26,17.78 50.8,17.78 53.34,17.78 53.34,20.32 53.34,22.86 55.88,22.86 55.88,20.32 58.42,20.32 58.42,22.86 55.88,17.78 58.42,17.78 60.96,17.78 60.96,20.32 60.96,22.86 48.26,15.24 48.26,12.7 50.8,12.7 50.8,15.24 48.26,10.16 50.8,10.16 53.34,10.16 53.34,12.7 53.34,15.24 55.88,15.24 55.88,12.7 58.42,12.7 58.42,15.24 55.88,10.16 58.42,10.16 60.96,10.16 60.96,12.7 60.96,15.24 63.5,22.86 63.5,20.32 66.04,20.32 66.04,22.86 63.5,17.78 66.04,17.78 68.58,17.78 68.58,20.32 68.58,22.86 71.12,22.86 71.12,20.32 73.66,20.32 73.66,22.86 71.12,17.78 73.66,17.78 76.2,17.78 76.2,20.32 76.2,22.86 63.5,15.24 63.5,12.7 66.04,12.7 66.04,15.24 63.5,10.16 66.04,10.16 68.58,10.16 68.58,12.7 68.58,15.24 71.12,15.24 71.12,12.7 73.66,12.7 73.66,15.24 71.12,10.16 73.66,10.16 76.2,10.16 76.2,12.7 76.2,15.24 78.74,22.86 78.74,20.32 81.28,20.32 81.28,22.86 78.74,17.78 81.28,17.78 83.82,17.78 83.82,20.32 83.82,22.86 86.36,22.86 86.36,20.32 88.9,20.32 88.9,22.86 86.36,17.78 88.9,17.78 91.44,17.78 91.44,20.32 91.44,22.86 78.74,15.24 78.74,12.7 81.28,12.7 81.28,15.24 78.74,10.16 81.28,10.16 83.82,10.16 83.82,12.7 83.82,15.24 86.36,15.24 86.36,12.7 88.9,12.7 88.9,15.24 86.36,10.16 88.9,10.16 91.44,10.16 91.44,12.7 91.44,15.24 93.98,22.86 93.98,20.32 96.52,20.32 96.52,22.86 93.98,17.78 96.52,17.78 99.06,17.78 99.06,20.32 99.06,22.86 101.6,22.86 101.6,20.32 104.14,20.32 104.14,22.86 101.6,17.78 104.14,17.78 106.68,17.78 106.68,20.32 106.68,22.86 93.98,15.24 93.98,12.7 96.52,12.7 96.52,15.24 93.98,10.16 96.52,10.16 99.06,10.16 99.06,12.7 99.06,15.24 101.6,15.24 101.6,12.7 104.14,12.7 104.14,15.24 101.6,10.16 104.14,10.16 106.68,10.16 106.68,12.7 106.68,15.24 109.22,17.78 109.22,20.32 109.22,22.86 111.76,22.86 111.76,20.32 114.3,20.32 114.3,22.86 111.76,17.78 114.3,17.78 109.22,10.16 109.22,12.7 109.22,15.24 111.76,15.24 111.76,12.7 114.3,12.7 114.3,15.24 111.76,10.16 114.3,10.16 33.02,7.62 33.02,5.08 35.56,5.08 35.56,7.62 33.02,2.54 35.56,2.54 38.1,2.54 38.1,5.08 38.1,7.62 40.64,7.62 40.64,5.08 43.18,5.08 43.18,7.62 40.64,2.54 43.18,2.54 45.72,2.54 45.72,5.08 45.72,7.62 48.26,7.62 48.26,5.08 50.8,5.08 50.8,7.62 48.26,2.54 50.8,2.54 53.34,2.54 53.34,5.08 53.34,7.62 55.88,7.62 55.88,5.08 58.42,5.08 58.42,7.62 55.88,2.54 58.42,2.54 60.96,2.54 60.96,5.08 60.96,7.62 63.5,7.62 63.5,5.08 66.04,5.08 66.04,7.62 63.5,2.54 66.04,2.54 68.58,2.54 68.58,5.08 68.58,7.62 71.12,7.62 71.12,5.08 73.66,5.08 73.66,7.62 71.12,2.54 73.66,2.54 76.2,2.54 76.2,5.08 76.2,7.62 78.74,7.62 78.74,5.08 81.28,5.08 81.28,7.62 78.74,2.54 81.28,2.54 83.82,2.54 83.82,5.08 83.82,7.62 86.36,7.62 86.36,5.08 88.9,5.08 88.9,7.62 86.36,2.54 88.9,2.54 91.44,2.54 91.44,5.08 91.44,7.62 93.98,7.62 93.98,5.08 96.52,5.08 96.52,7.62 93.98,2.54 96.52,2.54 99.06,2.54 99.06,5.08 99.06,7.62 101.6,7.62 101.6,5.08 104.14,5.08 104.14,7.62 101.6,2.54 104.14,2.54 106.68,2.54 106.68,5.08 106.68,7.62 109.22,2.54 109.22,5.08 109.22,7.62 111.76,7.62 111.76,5.08 114.3,5.08 114.3,7.62 111.76,2.54 114.3,2.54

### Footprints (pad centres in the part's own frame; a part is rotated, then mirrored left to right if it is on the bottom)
THRU-HOLE2 = drill 1.016 long: A1 28.575,9.525; A2 28.575,3.175; B1 25.4,12.7; B2 25.4,6.35; C1 22.225,9.525; C2 22.225,3.175; D1 19.05,12.7; D2 19.05,6.35; E1 15.875,9.525; E2 15.875,3.175; F1 12.7,12.7; F2 12.7,6.35; H1 9.525,9.525; H2 9.525,3.175; J1 6.35,12.7; J2 6.35,6.35; K1 3.175,9.525; K2 3.175,3.175; L1 0,12.7; L2 0,6.35; M1 -3.175,9.525; M2 -3.175,3.175; N1 -6.35,12.7; N2 -6.35,6.35; P1 -9.525,9.525; P2 -9.525,3.175; R1 -12.7,12.7; R2 -12.7,6.35; S1 -15.875,9.525; S2 -15.875,3.175; T1 -19.05,12.7; T2 -19.05,6.35; U1 -22.225,9.525; U2 -22.225,3.175; V1 -25.4,12.7; V2 -25.4,6.35
DOUBLE = hole 3.175: 120.65,56.515; 120.65,5.715; 120.65,74.93; 120.65,126.365
EDGE-CON4 = smd 13.017 x 2.032: AA1 7.709,4.207; AB1 7.684,7.312; AC1 7.684,10.474; AD1 7.684,13.665; AE1 7.693,16.84; AF1 7.668,20.041; AH1 7.668,23.19; AJ1 7.668,26.34; AK1 7.668,29.515; AL1 7.693,32.69; AM1 7.693,35.89; AN1 7.693,39.04; AP1 7.668,42.24; AR1 7.668,45.39; AS1 7.693,48.565; AT1 7.693,51.74; AU1 7.693,54.94; AV1 7.668,58.026; BA1 7.709,74.057; BB1 7.684,77.162; BC1 7.684,80.324; BD1 7.684,83.515; BE1 7.693,86.69; BF1 7.668,89.891; BH1 7.668,93.04; BJ1 7.668,96.19; BK1 7.668,99.365; BL1 7.693,102.54; BM1 7.693,105.74; BN1 7.693,108.89; BP1 7.668,112.09; BR1 7.668,115.24; BS1 7.693,118.415; BT1 7.693,121.59; BU1 7.693,124.79; BV1 7.668,127.876 | smd 13.017 x 2.032 bottom: AA2 7.69,4.207; AB2 7.668,7.328; AC2 7.668,10.49; AD2 7.693,13.665; AE2 7.693,16.84; AF2 7.642,20.041; AH2 7.642,23.19; AJ2 7.668,26.34; AK2 7.668,29.515; AL2 7.693,32.69; AM2 7.693,35.89; AN2 7.693,39.04; AP2 7.668,42.24; AR2 7.668,45.39; AS2 7.693,48.565; AT2 7.693,51.74; AU2 7.693,54.966; AV2 7.668,58.026; BA2 7.69,74.057; BB2 7.668,77.178; BC2 7.668,80.34; BD2 7.693,83.515; BE2 7.693,86.69; BF2 7.642,89.891; BH2 7.642,93.04; BJ2 7.668,96.19; BK2 7.668,99.365; BL2 7.693,102.54; BM2 7.693,105.74; BN2 7.693,108.89; BP2 7.668,112.09; BR2 7.668,115.24; BS2 7.693,118.415; BT2 7.693,121.59; BU2 7.693,124.816; BV2 7.668,127.876

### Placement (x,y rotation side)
A  15.88,32.38 270 top
B  15.88,102.87 270 top
U$1  0,0 0 top
U$2  0,0 0 top

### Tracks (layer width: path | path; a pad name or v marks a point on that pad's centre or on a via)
N$1
  Bottom 0.508: A.K2 17.78,29.21 13.98,29.21 13.96,29.21 U$2.AK2
N$2
  Bottom 0.508: A.J2 20.96,26.04 13.98,26.04 13.96,26.04 U$2.AJ2
N$3
  Bottom 0.508: A.H2 17.78,22.86 13.98,22.86 13.96,22.86 U$2.AH2
N$4
  Bottom 0.508: A.L2 20.96,32.38 13.98,32.38 13.96,32.39 U$2.AL2
N$5
  Bottom 0.508: A.M2 17.78,35.56 13.98,35.56 13.96,35.56 U$2.AM2
N$6
  Bottom 0.508: A.N2 20.96,38.73 13.98,38.73 13.96,38.74 U$2.AN2
N$7
  Bottom 0.508: A.P2 17.78,41.91 13.98,41.91 13.96,41.91 U$2.AP2
N$8
  Bottom 0.508: A.F2 20.96,19.68 13.98,19.68 13.96,19.69 U$2.AF2
N$9
  Bottom 0.508: A.E2 17.78,16.51 13.98,16.51 13.96,16.51 U$2.AE2
N$10
  Bottom 0.508: A.D2 20.96,13.34 13.98,13.34 13.96,13.34 U$2.AD2
N$11
  Bottom 0.508: A.C2 17.78,10.16 13.98,10.16 13.96,10.16 U$2.AC2
N$12
  Bottom 0.508: A.R2 20.96,45.09 13.98,45.09 13.96,45.09 U$2.AR2
N$13
  Bottom 0.508: A.S2 17.78,48.26 13.98,48.26 13.96,48.26 U$2.AS2
N$14
  Bottom 0.508: A.B2 20.96,6.99 13.99,6.99 13.96,6.99 U$2.AB2
N$15
  Bottom 0.508: A.A2 17.78,3.81 13.99,3.81 13.95,3.81 U$2.AA2
N$16
  Bottom 0.508: A.T2 20.96,51.44 13.98,51.44 13.96,51.44 U$2.AT2
N$17
  Bottom 0.508: A.U2 17.78,54.61 13.98,54.61 13.96,54.61 U$2.AU2
N$18
  Bottom 0.508: A.V2 20.96,57.78 13.98,57.78 13.96,57.78 U$2.AV2
N$19
  Top 0.508: A.A1 24.13,3.81 22.44,3.81 22.08,3.66 20.47,2.05 20.11,1.91 17.99,1.91 17.63,2.05 16.02,3.66 15.67,3.81 13.99,3.81 13.95,3.81 U$2.AA1
N$20
  Top 0.508: A.V1 27.31,57.78 25.61,57.78 25.25,57.93 23.64,59.54 23.29,59.69 20.53,59.69 20.17,59.54 19.2,58.57 18.84,58.42 13.99,58.42 13.96,58.42 U$2.AV1
N$21
  Top 0.508: A.U1 24.13,54.61 22.44,54.61 22.08,54.76 20.47,56.37 20.11,56.52 16.09,56.52 15.73,56.37 14.13,54.77 13.74,54.62 U$2.AU1
N$22
  Top 0.508: A.T1 27.31,51.44 25.61,51.44 25.25,51.58 23.64,53.19 23.29,53.34 21.17,53.34 20.81,53.19 20.47,52.85 20.11,52.7 14.01,52.7 13.93,52.7 U$2.AT1
N$23
  Top 0.508: A.S1 24.13,48.26 22.44,48.26 22.08,48.41 20.47,50.02 20.11,50.16 16.09,50.16 15.73,50.02 14.13,48.42 13.75,48.27 U$2.AS1
N$24
  Top 0.508: A.R1 27.31,45.09 25.61,45.09 25.25,45.23 23.64,46.84 23.29,46.99 21.17,46.99 20.81,46.84 20.47,46.5 20.11,46.35 14.01,46.35 13.93,46.35 U$2.AR1
N$25
  Top 0.508: A.P1 24.13,41.91 22.44,41.91 22.08,42.06 20.47,43.67 20.11,43.81 16.09,43.81 15.73,43.67 14.13,42.07 13.74,41.92 U$2.AP1
N$26
  Top 0.508: A.N1 27.31,38.73 25.61,38.73 25.25,38.88 23.64,40.49 23.29,40.64 21.17,40.64 20.81,40.49 20.47,40.15 20.11,40.01 14.01,40.01 13.93,40 U$2.AN1
N$27
  Top 0.508: A.M1 24.13,35.56 22.44,35.56 22.08,35.71 20.47,37.32 20.11,37.47 16.09,37.47 15.73,37.32 14.13,35.72 13.74,35.57 U$2.AM1
N$28
  Top 0.508: A.L1 27.31,32.38 25.61,32.38 25.25,32.53 23.64,34.14 23.29,34.29 21.17,34.29 20.81,34.14 20.47,33.8 20.11,33.66 14.01,33.66 13.93,33.65 U$2.AL1
N$29
  Top 0.508: A.K1 24.13,29.21 22.44,29.21 22.08,29.36 20.47,30.97 20.11,31.11 16.09,31.11 15.73,30.97 14.13,29.37 13.75,29.22 U$2.AK1
N$30
  Top 0.508: A.J1 27.31,26.04 25.61,26.04 25.25,26.18 23.64,27.79 23.29,27.94 21.17,27.94 20.81,27.79 20.47,27.45 20.11,27.3 14.01,27.3 13.93,27.3 U$2.AJ1
N$31
  Top 0.508: A.H1 24.13,22.86 22.44,22.86 22.08,23.01 20.47,24.62 20.11,24.77 16.09,24.77 15.73,24.62 14.13,23.02 13.74,22.87 U$2.AH1
N$32
  Top 0.508: A.F1 27.31,19.68 25.61,19.68 25.25,19.54 23.64,17.93 23.29,17.78 21.17,17.78 20.81,17.93 19.83,18.9 19.48,19.05 14.01,19.05 13.93,19.06 U$2.AF1
N$33
  Top 0.508: A.E1 24.13,16.51 22.44,16.51 22.08,16.36 20.47,14.75 20.11,14.61 16.72,14.61 16.36,14.75 14.13,16.99 13.75,17.13 U$2.AE1
N$34
  Top 0.508: A.D1 27.31,13.34 25.61,13.34 25.25,13.19 23.64,11.58 23.29,11.43 21.17,11.43 20.81,11.58 19.83,12.55 19.48,12.7 14.01,12.7 13.93,12.71 U$2.AD1
N$35
  Top 0.508: A.C1 24.13,10.16 22.44,10.16 22.08,10.01 20.47,8.4 20.11,8.26 16.72,8.26 16.36,8.4 14.13,10.63 13.75,10.78 U$2.AC1
N$36
  Top 0.508: A.B1 27.31,6.99 25.61,6.99 25.25,6.84 23.64,5.23 23.29,5.08 21.17,5.08 20.81,5.23 19.83,6.2 19.48,6.35 14.01,6.35 13.93,6.36 U$2.AB1
N$37
  Bottom 0.508: B.K2 17.78,99.69 13.98,99.69 13.96,99.69 U$2.BK2
N$38
  Bottom 0.508: B.J2 20.96,96.52 13.98,96.52 13.96,96.52 U$2.BJ2
N$39
  Bottom 0.508: B.H2 17.78,93.34 13.98,93.34 13.96,93.34 U$2.BH2
N$40
  Bottom 0.508: B.L2 20.96,102.87 13.98,102.87 13.96,102.87 U$2.BL2
N$41
  Bottom 0.508: B.M2 17.78,106.05 13.98,106.05 13.96,106.04 U$2.BM2
N$42
  Bottom 0.508: B.N2 20.96,109.22 13.98,109.22 13.96,109.22 U$2.BN2
N$43
  Bottom 0.508: B.P2 17.78,112.39 13.98,112.39 13.96,112.39 U$2.BP2
N$44
  Bottom 0.508: B.F2 20.96,90.17 13.98,90.17 13.96,90.17 U$2.BF2
N$45
  Bottom 0.508: B.E2 17.78,87 13.98,87 13.96,86.99 U$2.BE2
N$46
  Bottom 0.508: B.D2 20.96,83.82 13.98,83.82 13.96,83.82 U$2.BD2
N$47
  Bottom 0.508: B.C2 17.78,80.64 13.98,80.64 13.96,80.64 U$2.BC2
N$48
  Bottom 0.508: B.R2 20.96,115.57 13.98,115.57 13.96,115.57 U$2.BR2
N$49
  Bottom 0.508: B.S2 17.78,118.75 13.98,118.75 13.96,118.74 U$2.BS2
N$50
  Bottom 0.508: B.B2 20.96,77.47 13.98,77.47 13.96,77.47 U$2.BB2
N$51
  Bottom 0.508: B.A2 17.78,74.3 13.98,74.3 13.96,74.3 U$2.BA2
N$52
  Bottom 0.508: B.T2 20.96,121.92 13.98,121.92 13.96,121.92 U$2.BT2
N$53
  Bottom 0.508: B.U2 17.78,125.09 13.98,125.09 13.96,125.09 U$2.BU2
N$54
  Bottom 0.508: B.V2 20.96,128.27 13.99,128.27 13.96,128.27 U$2.BV2
N$55
  Top 0.508: B.A1 24.13,74.3 22.44,74.3 22.08,74.15 20.47,72.54 20.11,72.39 17.36,72.39 17,72.54 16.02,73.51 15.67,73.66 13.99,73.66 13.95,73.66 U$2.BA1
N$56
  Top 0.508: B.V1 27.31,128.27 25.61,128.27 25.25,128.42 23.64,130.03 23.29,130.18 21.17,130.18 20.81,130.03 19.2,128.42 18.84,128.27 13.99,128.27 13.96,128.27 U$2.BV1
N$57
  Top 0.508: B.U1 24.13,125.09 22.44,125.09 22.08,124.95 20.47,123.34 20.11,123.19 16.09,123.19 15.73,123.34 14.13,124.94 13.75,125.08 U$2.BU1
N$58
  Top 0.508: B.T1 27.31,121.92 25.61,121.92 25.25,121.77 23.64,120.16 23.29,120.02 21.17,120.02 20.81,120.16 20.47,120.5 20.11,120.65 14.01,120.65 13.93,120.66 U$2.BT1
N$59
  Top 0.508: B.S1 24.13,118.75 22.44,118.75 22.08,118.6 20.47,116.99 20.11,116.84 16.09,116.84 15.73,116.99 14.13,118.58 13.74,118.73 U$2.BS1
N$60
  Top 0.508: B.R1 27.31,115.57 25.61,115.57 25.25,115.42 23.64,113.81 23.29,113.67 21.17,113.67 20.81,113.81 20.47,114.15 20.11,114.3 14.01,114.3 13.93,114.31 U$2.BR1
N$61
  Top 0.508: B.P1 24.13,112.39 22.44,112.39 22.08,112.25 20.47,110.64 20.11,110.49 16.09,110.49 15.73,110.64 14.13,112.24 13.75,112.38 U$2.BP1
N$62
  Top 0.508: B.N1 27.31,109.22 25.61,109.22 25.25,109.07 23.64,107.46 23.29,107.31 21.17,107.31 20.81,107.46 20.47,107.8 20.11,107.95 14.01,107.95 13.93,107.96 U$2.BN1
N$63
  Top 0.508: B.M1 24.13,106.05 22.44,106.05 22.08,105.9 20.47,104.29 20.11,104.14 16.09,104.14 15.73,104.29 14.13,105.89 13.75,106.03 U$2.BM1
N$64
  Top 0.508: B.L1 27.31,102.87 25.61,102.87 25.25,102.72 23.64,101.11 23.29,100.97 21.17,100.97 20.81,101.11 20.47,101.45 20.11,101.6 14.01,101.6 13.93,101.61 U$2.BL1
N$65
  Top 0.508: B.K1 24.13,99.69 22.44,99.69 22.08,99.55 20.47,97.94 20.11,97.79 16.09,97.79 15.73,97.94 14.13,99.53 13.74,99.68 U$2.BK1
N$66
  Top 0.508: B.J1 27.31,96.52 25.61,96.52 25.25,96.37 23.64,94.76 23.29,94.61 21.17,94.61 20.81,94.76 20.47,95.1 20.11,95.25 14.01,95.25 13.93,95.26 U$2.BJ1
N$67
  Top 0.508: B.H1 24.13,93.34 22.44,93.34 22.08,93.2 20.47,91.59 20.11,91.44 16.09,91.44 15.73,91.59 14.13,93.19 13.75,93.33 U$2.BH1
N$68
  Top 0.508: B.F1 27.31,90.17 25.61,90.17 25.25,90.02 23.64,88.41 23.29,88.27 21.17,88.27 20.81,88.41 20.47,88.75 20.11,88.9 14.01,88.9 13.93,88.91 U$2.BF1
N$69
  Top 0.508: B.E1 24.13,87 22.44,87 22.08,86.85 20.47,85.24 20.11,85.09 16.09,85.09 15.73,85.24 14.13,86.84 13.75,86.98 U$2.BE1
N$70
  Top 0.508: B.D1 27.31,83.82 25.61,83.82 25.25,83.67 23.64,82.06 23.29,81.92 21.17,81.92 20.81,82.06 20.47,82.4 20.11,82.55 14.01,82.55 13.93,82.56 U$2.BD1
N$71
  Top 0.508: B.C1 24.13,80.64 22.44,80.64 22.08,80.5 20.47,78.89 20.11,78.74 16.09,78.74 15.73,78.89 14.13,80.48 13.75,80.63 U$2.BC1
N$72
  Top 0.508: B.B1 27.31,77.47 25.61,77.47 25.25,77.32 23.64,75.71 23.29,75.56 21.17,75.56 20.81,75.71 20.47,76.05 20.11,76.2 14.01,76.2 13.93,76.21 U$2.BB1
